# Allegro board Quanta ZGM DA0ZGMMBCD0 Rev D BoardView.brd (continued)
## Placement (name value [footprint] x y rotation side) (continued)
C515  100u/6.3V_12  [C1206]  23.57 55.15 0 top
C516  0.1u/6.3V_2  [C0201]  176.41 55.08 270 top
C517  *47u/6.3V_8  [C0805]  102.11 54.57 90 top
C518  *68p/25V_2  [C0201]  137.38 54.31 180 top
C519  *2.2u/10V_4  [C0402]  137.45 53.45 180 top
C520  470p/50V_4  [C0402]  20.23 53.25 270 top
C521  0.1u/6.3V_2  [C0201]  21.27 53.15 90 top
C522  *6.8p/50V_2  [C0201]  137.59 52.57 180 top
C523  *220p/25V_2  [C0201]  208.79 50.51 270 top
C524  *0.1u/6.3V_2  [C0201]  256.59 50.41 180 top
C525  0.1u/6.3V_2  [C0201]  21.41 48.59 0 top
C526  *0.1u/6.3V_2  [C0201]  212.2 47.79 180 top
C527  *68p/25V_2  [C0201]  137.78 47.68 180 top
C528  0.1u/6.3V_2  [C0201]  281.18 47.21 90 top
C529  0.1u/6.3V_2  [C0201]  281.94 47.21 90 top
C530  10u/6.3V_4  [C0402]  282.83 46.83 270 top
C531  *10u/6.3V_4  [C0402]  283.85 46.83 270 top
C532  *47u/6.3V_8  [C0805]  285.37 46.06 90 top
C533  *47u/6.3V_8  [C0805]  287.4 46.06 90 top
C534  0.1u/6.3V_2  [C0201]  193.55 45.56 270 top
C535  *6.8p/50V_2  [C0201]  271.06 45.42 90 top
C536  *68p/25V_2  [C0201]  271.77 45.41 90 top
C537  *2.2u/10V_4  [C0402]  225.4 45.26 90 top
C538  *220p/25V_2  [C0201]  207.78 45.25 90 top
C539  *68p/25V_2  [C0201]  224.53 45.22 90 top
C540  *68p/25V_2  [C0201]  226.28 45.18 90 top
C541  *1000p/25V_2  [C0201]  219.21 45.05 90 top
C542  0.1u/6.3V_2  [C0201]  183.01 44.92 0 top
C543  0.1u/6.3V_2  [C0201]  184.03 44.92 180 top
C544  0.1u/6.3V_2  [C0201]  17.02 42.7 0 top
C545  *1000p/25V_2  [C0201]  187.2 42.51 0 top
C546  220p/25V_2  [C0201]  13.74 41.85 90 top
C547  0.1u/6.3V_2  [C0201]  219.84 41.49 180 top
C548  0.1u/6.3V_2  [C0201]  217.55 41.2 180 top
C549  *6.8p/50V_2  [C0201]  285.64 40.09 270 top
C550  *6.8p/50V_2  [C0201]  286.36 40.07 270 top
C551  *1000p/25V_2  [C0201]  203.91 39.38 180 top
C552  0.1u/6.3V_2  [C0201]  206.17 39.08 180 top
C553  *220p/25V_2  [C0201]  13.97 38.7 90 top
C554  0.1u/6.3V_2  [C0201]  23.91 24.37 270 top
C555  0.1u/6.3V_2  [C0201]  24.15 21.97 180 top
C556  0.1u/6.3V_2  [C0201]  24.15 21.26 180 top
C557  10u/6.3V_4  [C0402]  16.87 21.17 270 top
C558  0.1u/6.3V_2  [C0201]  15.91 20.8 90 top
C559  220p/25V_2  [C0201]  19.49 10.39 270 top
C560  0.1u/6.3V_2  [C0201]  18.57 6.86 180 top
C561  0.1u/6.3V_2  [C0201]  19.56 6.86 0 top
C562  0.01u/50V_4  [C0402]  16.7 3.06 0 top
C563  0.01u/50V_4  [C0402]  19.87 3.06 180 top
C564  0.1u/6.3V_2  [C0201]  262.54 217.49 0 bottom
C565  0.1u/6.3V_2  [C0201]  277.71 216.02 270 bottom
C566  0.1u/6.3V_2  [C0201]  278.43 216.02 270 bottom
C567  0.1u/6.3V_2  [C0201]  274.85 216.02 270 bottom
C568  0.1u/6.3V_2  [C0201]  275.56 216.02 270 bottom
C569  0.1u/6.3V_2  [C0201]  276.28 216.02 270 bottom
C570  0.1u/6.3V_2  [C0201]  276.99 216.02 270 bottom
C571  0.1u/6.3V_2  [C0201]  271.99 215.95 270 bottom
C572  0.1u/6.3V_2  [C0201]  272.7 215.95 270 bottom
C573  0.1u/6.3V_2  [C0201]  270.24 215.57 270 bottom
C574  0.1u/6.3V_2  [C0201]  270.95 215.57 270 bottom
C575  0.1u/6.3V_2  [C0201]  142.75 214.34 270 bottom
C576  10u/6.3V_4  [C0402]  143.89 214.34 90 bottom
C577  0.1u/6.3V_2  [C0201]  269.85 213.58 0 bottom
C578  2200p/25V_2  [C0201]  259.82 213.15 0 bottom
C579  0.1u/6.3V_2  [C0201]  269.85 212.81 0 bottom
C580  0.1u/6.3V_2  [C0201]  269.85 212.1 0 bottom
C581  0.1u/6.3V_2  [C0201]  269.85 211.33 0 bottom
C582  0.1u/6.3V_2  [C0201]  272.67 209.12 270 bottom
C583  0.1u/6.3V_2  [C0201]  273.43 209.12 270 bottom
C584  0.1u/6.3V_2  [C0201]  271.19 209.12 270 bottom
C585  0.1u/6.3V_2  [C0201]  271.96 209.12 270 bottom
C586  0.1u/6.3V_2  [C0201]  275.35 209.09 270 bottom
C587  0.1u/6.3V_2  [C0201]  276.11 209.09 270 bottom
C588  0.1u/6.3V_2  [C0201]  276.82 209.09 270 bottom
C589  0.1u/6.3V_2  [C0201]  277.59 209.09 270 bottom
C590  0.1u/6.3V_2  [C0201]  278.31 209.09 90 bottom
C591  0.1u/6.3V_2  [C0201]  279.07 209.09 90 bottom
C592  10u/6.3V_4  [C0402]  145.91 208.04 90 bottom
C593  0.1u/6.3V_2  [C0201]  144.76 208.03 270 bottom
C594  0.1u/6.3V_2  [C0201]  266.36 207.74 270 bottom
C595  0.1u/6.3V_2  [C0201]  267.12 207.74 90 bottom
C596  *2.2u/10V_4  [C0402]  278.07 204.64 270 bottom
C597  1u/10V_2  [C0201]  286.51 202.24 270 bottom
C598  0.1u/6.3V_2  [C0201]  280.74 201.42 180 bottom
C599  0.1u/6.3V_2  [C0201]  268.13 200.65 90 bottom
C600  10u/6.3V_4  [C0402]  280.78 200.43 0 bottom
C601  0.1u/6.3V_2  [C0201]  268.13 198.87 270 bottom
C602  180p/25V_2  [C0201]  270.01 196.69 270 bottom
C603  *2.2u/25V_4  [C0402]  193.7 194.51 270 bottom
C604  *3.3p/25V_2  [C0201]  193.04 193.28 0 bottom
C605  *68p/25V_2  [C0201]  193.04 192.51 0 bottom
C606  0.1u/6.3V_2  [C0201]  269.08 185.98 270 bottom
C607  10u/25V_8  [C0805]  275.47 184.11 180 bottom
C608  *6.8p/50V_2  [C0201]  270.03 185.48 270 bottom
C609  1000p/25V_2  [C0201]  267.68 185.36 90 bottom
C610  *6.8p/50V_2  [C0201]  270.84 184.67 90 bottom
C611  22u/6.3V_6  [C0603]  202.87 183.91 0 bottom
C612  0.1u/6.3V_2  [C0201]  200.79 183.73 0 bottom
C613  0.1u/25V_2  [C0201]  270.01 183.6 90 bottom
C614  100p/50V_2  [C0201]  270.89 183.22 270 bottom
C615  10u/25V_8  [C0805]  273.38 181.37 0 bottom
C616  *10u/6.3V_4  [C0402]  198.55 182.46 0 bottom
C617  22u/6.3V_6  [C0603]  210.7 182.21 180 bottom
C618  0.047u/6.3V_2  [C0201]  200.88 181.97 90 bottom
C619  *1000p/25V_2  [C0201]  200.76 181.05 180 bottom
C620  0.1u/6.3V_2  [C0201]  206.57 175.48 270 bottom
C621  *10u/6.3V_4  [C0402]  205.51 175.38 90 bottom
C622  *68p/25V_2  [C0201]  111.27 175.3 270 bottom
C623  *68p/25V_2  [C0201]  112.04 175.29 270 bottom
C624  *2.2u/10V_4  [C0402]  110.34 175.27 270 bottom
C625  *6.8p/50V_2  [C0201]  206.98 173.41 90 bottom
C626  *6.8p/50V_2  [C0201]  206.01 173.39 90 bottom
C627  *6.8p/50V_2  [C0201]  262.67 172.08 0 bottom
C628  *6.8p/50V_2  [C0201]  262.68 171.32 0 bottom
C629  *2.2u/10V_4  [C0402]  149.49 168.23 0 bottom
C630  *6.8p/50V_2  [C0201]  149.46 167.36 0 bottom
C631  *6.8p/50V_2  [C0201]  149.47 166.55 0 bottom
C632  2200p/25V_2  [C0201]  189.49 166.3 90 bottom
C633  47u/6.3V_6  [C0603]  132.84 163.11 180 bottom
C634  0.1u/6.3V_2  [C0201]  150.16 162.11 90 bottom
C635  0.1u/6.3V_2  [C0201]  151.31 162.11 90 bottom
C636  0.1u/6.3V_2  [C0201]  152.63 161.82 90 bottom
C637  0.1u/6.3V_2  [C0201]  153.39 161.82 90 bottom
C638  0.1u/6.3V_2  [C0201]  155.72 161.67 90 bottom
C639  0.1u/6.3V_2  [C0201]  156.49 161.67 90 bottom
C640  0.1u/6.3V_2  [C0201]  159.03 161.67 90 bottom
C641  0.1u/6.3V_2  [C0201]  159.79 161.67 90 bottom
C642  0.1u/6.3V_2  [C0201]  161.62 161.63 90 bottom
C643  0.1u/6.3V_2  [C0201]  162.39 161.63 90 bottom
C644  47u/6.3V_6  [C0603]  127.18 161.51 180 bottom
C645  47u/6.3V_6  [C0603]  138.9 161.27 180 bottom
C646  0.1u/6.3V_2  [C0201]  157.36 160.83 90 bottom
C647  0.1u/6.3V_2  [C0201]  158.12 160.83 90 bottom
C648  47u/6.3V_6  [C0603]  132.76 160.81 180 bottom
C649  0.1u/6.3V_2  [C0201]  160.4 160.31 90 bottom
C650  0.1u/6.3V_2  [C0201]  161.16 160.31 90 bottom
C651  0.1u/6.3V_2  [C0201]  162.69 160.24 90 bottom
C652  0.1u/6.3V_2  [C0201]  163.45 160.24 90 bottom
C653  47u/6.3V_6  [C0603]  127.18 159.99 180 bottom
C654  47u/6.3V_6  [C0603]  139 159.16 180 bottom
C655  10p/25V_2  [C0201]  166.34 158.75 0 bottom
C656  10p/25V_2  [C0201]  166.34 157.86 0 bottom
C657  8.2p/50V_2  [C0201]  166.34 156.97 0 bottom
C658  10p/25V_2  [C0201]  123.59 155.57 270 bottom
C659  10p/25V_2  [C0201]  124.36 155.57 270 bottom
C660  47u/6.3V_6  [C0603]  122.36 151.68 270 bottom
C661  47u/6.3V_6  [C0603]  123.91 151.65 270 bottom
C662  47u/6.3V_6  [C0603]  120.5 147.44 270 bottom
C663  47u/6.3V_6  [C0603]  121.93 147.07 270 bottom
C664  0.1u/6.3V_2  [C0201]  114.4 144.32 90 bottom
C665  0.22u/6.3V_2  [C0201]  182.01 141.78 0 bottom
C666  0.22u/6.3V_2  [C0201]  182.01 141.02 0 bottom
C667  0.22u/6.3V_2  [C0201]  183.41 140.61 0 bottom
C668  0.22u/6.3V_2  [C0201]  183.41 139.85 0 bottom
C669  0.22u/6.3V_2  [C0201]  182.01 139.44 0 bottom
C670  0.22u/6.3V_2  [C0201]  182.01 138.68 0 bottom
C671  *6.8p/50V_2  [C0201]  276.14 138.55 270 bottom
C672  *6.8p/50V_2  [C0201]  275.33 138.54 270 bottom
C673  0.22u/6.3V_2  [C0201]  183.41 138.28 0 bottom
C674  0.22u/6.3V_2  [C0201]  183.41 137.51 0 bottom
C675  0.22u/6.3V_2  [C0201]  182.01 137.11 0 bottom
C676  0.22u/6.3V_2  [C0201]  182.01 136.35 0 bottom
C677  0.22u/6.3V_2  [C0201]  183.41 135.94 0 bottom
C678  0.22u/6.3V_2  [C0201]  183.41 135.18 0 bottom
C679  0.22u/6.3V_2  [C0201]  182.01 134.77 0 bottom
C680  0.22u/6.3V_2  [C0201]  182.01 134.01 0 bottom
C681  0.22u/6.3V_2  [C0201]  181.65 132.4 270 bottom
C682  0.22u/6.3V_2  [C0201]  182.41 132.4 270 bottom
C683  *6.8p/50V_2  [C0201]  197.26 128.35 180 bottom
C684  *6.8p/50V_2  [C0201]  197.25 127.54 180 bottom
C685  6.8p/50V_2  [C0201]  237.24 121.37 180 bottom
C686  *2.2u/10V_4  [C0402]  289.57 111.25 90 bottom
C687  *6.8p/50V_2  [C0201]  288.51 111.07 90 bottom
C688  *68p/25V_2  [C0201]  287.77 111.06 90 bottom
C689  2200p/25V_2  [C0201]  212.6 107.03 0 bottom
C690  220p/25V_2  [C0201]  106.77 104.88 90 bottom
C691  220p/25V_2  [C0201]  108.04 104.88 90 bottom
C692  0.1u/25V_2  [C0201]  109.31 104.88 270 bottom
C693  0.1u/6.3V_2  [C0201]  210.41 102.94 270 bottom
C694  0.1u/6.3V_2  [C0201]  309.41 99.29 270 bottom
C695  10u/6.3V_4  [C0402]  310.28 99.14 90 bottom
C696  0.1u/6.3V_2  [C0201]  311.12 98.53 90 bottom
C697  10u/6.3V_4  [C0402]  311.95 98.54 270 bottom
C698  0.1u/6.3V_2  [C0201]  309.32 96.47 270 bottom
C699  10u/6.3V_4  [C0402]  310.39 96.47 90 bottom
C700  10u/6.3V_4  [C0402]  36.11 95.76 180 bottom
C701  10u/6.3V_4  [C0402]  39.63 95.31 0 bottom
C702  2.2u/10V_4  [C0402]  36.11 94.79 180 bottom
C703  *3.3p/25V_2  [C0201]  95.25 94.38 180 bottom
C704  2.2u/10V_4  [C0402]  39.63 94.32 0 bottom
C705  *6.8p/50V_2  [C0201]  78.11 93.97 0 bottom
C706  18p/25V_2  [C0201]  36.41 93.96 0 bottom
C707  *68p/25V_2  [C0201]  95.25 93.61 180 bottom
C708  2.2u/10V_4  [C0402]  41.43 92.79 90 bottom
C709  *2.2u/10V_4  [C0402]  95.19 92.74 180 bottom
C710  47u/6.3V_6  [C0603]  36.44 92.28 270 bottom
C711  *68p/25V_2  [C0201]  49.22 91.79 180 bottom
C712  2.2u/10V_4  [C0402]  41.57 91.07 270 bottom
C713  *2.2u/10V_4  [C0402]  49.24 90.92 180 bottom
C714  10u/6.3V_4  [C0402]  312.35 89.92 0 bottom
C715  2.2u/10V_4  [C0402]  38.87 90.4 270 bottom
C716  5G@1u/10V_2  [C0201]  299.05 90.39 180 bottom
C717  2.2u/10V_4  [C0402]  36.44 90.11 90 bottom
C718  2.2u/10V_4  [C0402]  40.22 90.05 180 bottom
C719  *3.3p/25V_2  [C0201]  49.22 90.04 180 bottom
C720  0.1u/6.3V_2  [C0201]  313.67 89.83 270 bottom
C721  5G@0.22u/6.3V_2  [C0201]  310.65 89.42 0 bottom
C722  2.2u/10V_4  [C0402]  41.57 89.33 270 bottom
C723  5G@0.22u/6.3V_2  [C0201]  310.65 88.66 0 bottom
C724  2.2u/10V_4  [C0402]  36.44 88.38 270 bottom
C725  0.22u/6.3V_2  [C0201]  113.03 88.23 0 bottom
C726  0.22u/6.3V_2  [C0201]  113.03 87.47 0 bottom
C727  0.22u/6.3V_2  [C0201]  113.03 85.18 0 bottom
C728  *22p/25V_2  [C0201]  216.94 84.81 0 bottom
C729  *47p/25V_2  [C0201]  215.12 84.75 90 bottom
C730  0.22u/6.3V_2  [C0201]  113.03 84.42 0 bottom
C731  *0.1u/6.3V_2  [C0201]  214.02 83.99 180 bottom
C732  0.22u/6.3V_2  [C0201]  113.03 82.13 0 bottom
C733  0.22u/6.3V_2  [C0201]  113.03 81.37 0 bottom
C734  *2.2u/10V_4  [C0402]  100.16 80.94 90 bottom
C735  *68p/25V_2  [C0201]  99.3 80.56 90 bottom
C736  *6.8p/50V_2  [C0201]  98.58 80.56 90 bottom
C737  4.7u/6.3V_4  [C0402]  227.85 80.19 180 bottom
C738  0.22u/6.3V_2  [C0201]  113.03 79.08 0 bottom
C739  2.2u/10V_4  [C0402]  227.84 78.83 180 bottom
C740  0.22u/6.3V_2  [C0201]  113.03 78.32 0 bottom
C741  10u/6.3V_4  [C0402]  31.5 78.07 180 bottom
C742  2.2u/10V_4  [C0402]  35.06 78.04 0 bottom
C743  2.2u/10V_4  [C0402]  31.5 77.06 180 bottom
C744  10u/6.3V_4  [C0402]  35.06 77.05 0 bottom
C745  18p/25V_2  [C0201]  31.85 76.21 0 bottom
C746  2.2u/10V_4  [C0402]  36.86 75.52 90 bottom
C747  47u/6.3V_6  [C0603]  31.87 74.54 270 bottom
C748  *SUB@1000p/25V_2  [C0201]  290.15 74.39 270 bottom
C749  10u/6.3V_4  [C0402]  314.45 73.93 90 bottom
C750  2.2u/10V_4  [C0402]  36.86 73.72 270 bottom
C751  2.2u/10V_4  [C0402]  34.16 73.12 270 bottom
C752  2.2u/10V_4  [C0402]  35.51 72.78 180 bottom
C753  2.2u/10V_4  [C0402]  32.07 72.74 180 bottom
C754  2.2u/10V_4  [C0402]  36.86 71.99 270 bottom
C755  10u/6.3V_4  [C0402]  314.35 71.88 90 bottom
C756  2.2u/10V_4  [C0402]  31.97 71.09 270 bottom
C757  *SUB@1000p/25V_2  [C0201]  286.9 71.59 0 bottom
C758  *3.3p/25V_2  [C0201]  48.5 70.15 90 bottom
C759  *2.2u/10V_4  [C0402]  49.4 70.12 90 bottom
C760  *68p/25V_2  [C0201]  50.28 70.1 90 bottom
C761  *2.2u/10V_4  [C0402]  70.48 70 90 bottom
C762  0.1u/6.3V_2  [C0201]  314.34 69.94 180 bottom
C763  *3.3p/25V_2  [C0201]  71.39 69.93 90 bottom
C764  *68p/25V_2  [C0201]  69.59 69.9 90 bottom
C765  0.1u/6.3V_2  [C0201]  284.31 67.74 270 bottom
C766  0.1u/6.3V_2  [C0201]  285.07 67.74 270 bottom
C767  1u/10V_2  [C0201]  19.46 66.33 270 bottom
C768  1u/10V_2  [C0201]  21.11 66.33 270 bottom
C769  *68p/25V_2  [C0201]  96.5 66.26 270 bottom
C770  *6.8p/50V_2  [C0201]  97.26 66.26 270 bottom
C771  *2.2u/10V_4  [C0402]  98.12 66.23 270 bottom
C772  *0.1u/6.3V_2  [C0201]  314.76 65.62 180 bottom
C773  *10u/6.3V_4  [C0402]  310.29 65.53 0 bottom
C774  SUB@0.1u/6.3V_2  [C0201]  298.05 63.95 0 bottom
C775  10u/6.3V_4  [C0402]  311.34 63.21 90 bottom
C776  0.1u/6.3V_2  [C0201]  312.3 63.16 270 bottom
C777  0.22u/6.3V_2  [C0201]  112.4 62.83 0 bottom
C778  10u/6.3V_4  [C0402]  314.51 62.55 180 bottom
C779  0.1u/6.3V_2  [C0201]  18.95 62.17 90 bottom
C780  0.01u/10V_2  [C0201]  19.71 62.17 90 bottom
C781  0.22u/6.3V_2  [C0201]  112.4 62.07 0 bottom
C782  *1000p/25V_2  [C0201]  307.93 60.11 90 bottom
C783  0.22u/6.3V_2  [C0201]  112.4 59.78 0 bottom
C784  0.1u/6.3V_2  [C0201]  38.81 59.68 270 bottom
C785  0.1u/6.3V_2  [C0201]  40.34 59.68 270 bottom
C786  0.1u/6.3V_2  [C0201]  41.73 59.68 270 bottom
C787  0.1u/6.3V_2  [C0201]  43.38 59.68 270 bottom
C788  0.1u/6.3V_2  [C0201]  44.58 59.65 270 bottom
C789  5G@0.1u/25V_2  [C0201]  235.33 59.3 270 bottom
C790  0.1u/6.3V_2  [C0201]  191.15 59.24 0 bottom
C791  0.22u/6.3V_2  [C0201]  112.4 59.02 0 bottom
C792  *10p/25V_2  [C0201]  227.84 58.76 180 bottom
C793  5G@1u/10V_2  [C0201]  236.07 59.3 270 bottom
C794  0.1u/6.3V_2  [C0201]  21.23 58.13 270 bottom
C795  22p/25V_2  [C0201]  245.18 57.21 90 bottom
C796  0.1u/6.3V_2  [C0201]  246.81 57.06 90 bottom
C797  0.1u/6.3V_2  [C0201]  40.34 56.89 90 bottom
C798  0.1u/6.3V_2  [C0201]  43.38 56.89 90 bottom
C799  0.1u/6.3V_2  [C0201]  38.36 56.86 90 bottom
C800  0.1u/6.3V_2  [C0201]  39.37 56.86 90 bottom
C801  0.1u/6.3V_2  [C0201]  41.66 56.86 90 bottom
C802  4.7u/6.3V_4  [C0402]  42.55 56.86 270 bottom
C803  0.1u/6.3V_2  [C0201]  44.45 56.86 90 bottom
C804  0.22u/6.3V_2  [C0201]  112.4 56.73 0 bottom
C805  5G_S@0.1u/25V_2  [C0201]  279.68 56.45 0 bottom
C806  0.22u/6.3V_2  [C0201]  112.4 55.97 0 bottom
C807  0.1u/6.3V_2  [C0201]  227.59 55.97 90 bottom
C808  1u/10V_2  [C0201]  228.48 55.97 90 bottom
C809  5G_S@0.1u/25V_2  [C0201]  286.29 55.74 0 bottom
C810  5G_S@0.1u/25V_2  [C0201]  279.68 55.69 0 bottom
C811  10u/6.3V_4  [C0402]  98.81 55.08 0 bottom
C812  *6.8p/50V_2  [C0201]  19.18 55 270 bottom
C813  5G_S@0.1u/25V_2  [C0201]  286.29 54.98 0 bottom
C814  0.1u/6.3V_2  [C0201]  228.65 54.56 90 bottom
C815  10u/6.3V_4  [C0402]  227.55 54.56 270 bottom
C816  0.1u/6.3V_2  [C0201]  98.81 53.94 0 bottom
C817  1u/10V_2  [C0201]  25.44 53.89 270 bottom
C818  0.22u/6.3V_2  [C0201]  112.4 53.68 0 bottom
C819  *3.3p/25V_2  [C0201]  77.67 53.34 180 bottom
C820  0.1u/6.3V_2  [C0201]  98.81 53.18 0 bottom
C821  0.22u/6.3V_2  [C0201]  112.4 52.92 0 bottom
C822  0.033u/6.3V_2  [C0201]  211.55 52.42 270 bottom
C823  *2.2u/10V_4  [C0402]  77.68 52.42 180 bottom
C824  1u/10V_2  [C0201]  228.83 52.19 0 bottom
C825  1u/10V_2  [C0201]  230.13 52.16 270 bottom
C826  *3.3p/25V_2  [C0201]  77.66 51.51 180 bottom
C827  0.1u/6.3V_2  [C0201]  98.81 51.27 0 bottom
C828  15p/25V_2  [C0201]  218.62 50.77 0 bottom
C829  15p/25V_2  [C0201]  219.61 50.77 180 bottom
C830  0.1u/6.3V_2  [C0201]  98.81 50.51 0 bottom
C831  0.1u/6.3V_2  [C0201]  273.18 50.13 90 bottom
C832  0.1u/6.3V_2  [C0201]  273.94 50.13 90 bottom
C833  0.1u/6.3V_2  [C0201]  268.87 50.09 180 bottom
C834  1u/10V_2  [C0201]  230.13 49.87 90 bottom
C835  0.1u/6.3V_2  [C0201]  268.87 49.33 180 bottom
C836  0.1u/6.3V_2  [C0201]  276.48 49.24 0 bottom
C837  1u/10V_2  [C0201]  233.56 49.11 180 bottom
C838  0.1u/6.3V_2  [C0201]  276.48 48.35 0 bottom
C839  0.1u/6.3V_2  [C0201]  276.48 47.46 180 bottom
C840  18p/25V_2  [C0201]  220.07 45.78 270 bottom
C841  *1000p/25V_2  [C0201]  260.1 45.3 0 bottom
C842  *1000p/25V_2  [C0201]  262.13 45.3 180 bottom
C843  *1000p/25V_2  [C0201]  263.66 45.3 0 bottom
C844  *1000p/25V_2  [C0201]  265.56 45.3 180 bottom
C845  10u/6.3V_4  [C0402]  268.99 44.92 0 bottom
C846  0.1u/6.3V_2  [C0201]  271.53 42.76 90 bottom
C847  0.1u/6.3V_2  [C0201]  272.42 42.76 90 bottom
C848  0.1u/6.3V_2  [C0201]  273.31 42.76 90 bottom
C849  0.1u/6.3V_2  [C0201]  274.2 42.76 90 bottom
C850  0.1u/6.3V_2  [C0201]  18.62 27.14 270 bottom
C851  0.1u/6.3V_2  [C0201]  19.38 27.14 270 bottom
C852  0.1u/6.3V_2  [C0201]  20.15 27.14 270 bottom
C853  0.1u/6.3V_2  [C0201]  20.91 27.14 270 bottom
C854  0.1u/6.3V_2  [C0201]  21.67 27.14 270 bottom
C855  0.1u/6.3V_2  [C0201]  22.43 27.14 270 bottom
C856  0.1u/6.3V_2  [C0201]  23.19 27.14 270 bottom
C857  0.1u/6.3V_2  [C0201]  23.96 27.14 270 bottom
C858  *1u/10V_2  [C0201]  16.45 24.33 90 bottom
C859  0.1u/6.3V_2  [C0201]  17.22 24.33 90 bottom
C860  10u/6.3V_4  [C0402]  16.47 21.28 0 bottom
C861  0.1u/6.3V_2  [C0201]  19.19 18.25 90 bottom
C862  0.1u/6.3V_2  [C0201]  18.48 18.25 90 bottom
C863  0.1u/6.3V_2  [C0201]  22.62 18.25 90 bottom
C864  0.1u/6.3V_2  [C0201]  23.38 18.25 90 bottom
C865  0.1u/6.3V_2  [C0201]  21.25 18.25 90 bottom
C866  0.1u/6.3V_2  [C0201]  24.68 18.25 90 bottom
C867  0.1u/6.3V_2  [C0201]  25.44 18.25 90 bottom
C868  0.1u/6.3V_2  [C0201]  20.53 18.24 90 bottom
C871  0.22u/25V_2  [C0201]  202.95 73.88 90 top
C872  0.22u/25V_2  [C0201]  198.56 74.21 90 top
C873  *6.8p/50V_2  [C0201]  99.75 116.86 180 bottom
C874  *4.7u/6.3V_4  [C0402]  191.04 40.58 270 top
C875  *4.7u/6.3V_4  [C0402]  214.66 39.87 180 top
CG1  22u/6.3V_6  [C0603]  219.65 184.59 180 top
CG2  22u/6.3V_6  [C0603]  234.12 184.56 180 top
CG3  22u/6.3V_6  [C0603]  242.57 184.55 0 top
CG4  22u/6.3V_6  [C0603]  256.96 184.52 0 top
CG5  22u/6.3V_6  [C0603]  248.26 184.49 180 top
CG6  1u/10V_2  [C0201]  221.59 184.28 180 top
CG7  1u/10V_2  [C0201]  254.28 184.27 0 top
CG8  1u/10V_2  [C0201]  250.62 184.25 180 top
CG9  1u/10V_2  [C0201]  237.26 183.7 90 top
CG10  1u/10V_2  [C0201]  229.39 183.28 270 top
CG11  1u/10V_2  [C0201]  238.83 183.24 270 top
CG12  1u/10V_2  [C0201]  246.51 183.17 0 top
CG13  1u/10V_2  [C0201]  244.62 183.06 270 top
CG14  1u/10V_2  [C0201]  251.72 182.54 270 top
CG15  22u/6.3V_6  [C0603]  252.82 182.53 90 top
CG16  1u/10V_2  [C0201]  224.13 182.36 270 top
CG17  10u/6.3V_4  [C0402]  223.04 182.15 90 top
CG18  1u/10V_2  [C0201]  250.81 182.03 270 top
CG19  10u/6.3V_4  [C0402]  217.23 181.98 270 top
CG20  1u/10V_2  [C0201]  244 181.74 90 top
CG21  1u/10V_2  [C0201]  246.54 181.69 270 top
CG22  1u/10V_2  [C0201]  240.15 181.5 180 top
CG23  22u/6.3V_6  [C0603]  258.94 181.38 90 top
CG24  1u/10V_2  [C0201]  221.28 181.35 180 top
CG25  1u/10V_2  [C0201]  254.79 181.33 0 top
CG26  1u/10V_2  [C0201]  235.65 181.32 270 top
CG27  1u/10V_2  [C0201]  229.53 181.09 270 top
CG28  1u/10V_2  [C0201]  240.1 180.58 180 top
CG29  1u/10V_2  [C0201]  243.92 180.24 90 top
CG30  22u/6.3V_6  [C0603]  231.67 180.21 90 top
CG31  1u/10V_2  [C0201]  246.4 180.17 270 top
CG32  1u/10V_2  [C0201]  217.46 180.1 90 top
CG33  1u/10V_2  [C0201]  253.09 179.96 90 top
CG34  1u/10V_2  [C0201]  237.44 179.92 90 top
CG35  1u/10V_2  [C0201]  258.59 179.58 270 top
CG36  1u/10V_2  [C0201]  229.47 179.56 270 top
CG37  1u/10V_2  [C0201]  243.21 179.27 0 top
CG38  1u/10V_2  [C0201]  255.07 179.24 0 top
CG39  1u/10V_2  [C0201]  226.21 179.07 0 top
CG40  1u/10V_2  [C0201]  217.41 178.7 90 top
CG41  1u/10V_2  [C0201]  246.48 178.6 90 top
CG42  1u/10V_2  [C0201]  229.56 178.24 90 top
CG43  1u/10V_2  [C0201]  257.01 178.14 180 top
CG44  1u/10V_2  [C0201]  231.99 177.93 90 top
CG45  22u/6.3V_6  [C0603]  258.91 177.76 90 top
CG46  1u/10V_2  [C0201]  248.77 177.57 0 top
CG47  1u/10V_2  [C0201]  247.77 177.57 0 top
CG48  1u/10V_2  [C0201]  241.38 177.5 180 top
CG49  1u/10V_2  [C0201]  219.31 177.39 0 top
CG50  1u/10V_2  [C0201]  242.16 176.1 180 top
CG51  1u/10V_2  [C0201]  218.63 176 0 top
CG52  1u/10V_2  [C0201]  237.97 175.99 90 top
CG53  1u/10V_2  [C0201]  233.17 175.98 270 top
CG54  22u/6.3V_6  [C0603]  259.14 175.09 90 top
CG55  1u/10V_2  [C0201]  232.02 175.08 270 top
CG56  1u/10V_2  [C0201]  228.12 175.06 90 top
CG57  1u/10V_2  [C0201]  226.31 174.59 90 top
CG58  10u/6.3V_4  [C0402]  252.93 173.75 270 top
CG59  1u/10V_2  [C0201]  217.49 173.64 90 top
CG60  1u/10V_2  [C0201]  232.02 173.58 90 top
CG61  22u/6.3V_6  [C0603]  244.48 173.41 270 top
CG62  22u/6.3V_6  [C0603]  246.2 173.41 270 top
CG63  1u/10V_2  [C0201]  215.38 173.26 90 top
CG64  1u/10V_2  [C0201]  235.81 173.26 0 top
CG65  1u/10V_2  [C0201]  250.26 173.23 180 top
CG66  1u/10V_2  [C0201]  221.5 173.17 0 top
CG67  1u/10V_2  [C0201]  254.68 173.1 0 top
CG68  1u/10V_2  [C0201]  229.64 172.75 270 top
CG69  1u/10V_2  [C0201]  258.49 172.73 270 top
CG70  1u/10V_2  [C0201]  217.41 172.59 90 top
CG71  1u/10V_2  [C0201]  235.81 172.52 0 top
CG72  1u/10V_2  [C0201]  252.13 172.46 180 top
CG73  1u/10V_2  [C0201]  250.4 172.42 0 top
CG74  1u/10V_2  [C0201]  196.81 168.05 270 top
CG75  1u/10V_2  [C0201]  197.76 167.28 180 top
CG76  1u/10V_2  [C0201]  199.46 166.06 270 top
CG77  1u/10V_2  [C0201]  275.05 165.77 270 top
CG78  1u/10V_2  [C0201]  197.65 165.72 180 top
CG79  1u/10V_2  [C0201]  275.17 164.72 270 top
CG80  1u/10V_2  [C0201]  198.14 164.5 270 top
CG81  1u/10V_2  [C0201]  202.73 163.6 270 top
CG82  1u/10V_2  [C0201]  199.74 163.25 90 top
CG83  1u/10V_2  [C0201]  272.35 162.83 90 top
CG84  1u/10V_2  [C0201]  274.51 161.52 0 top
CG85  1u/10V_2  [C0201]  198.33 161.45 270 top
CG86  1u/10V_2  [C0201]  200.3 161.42 180 top
CG87  1u/10V_2  [C0201]  273.43 161.34 180 top
CG88  1u/10V_2  [C0201]  270.76 161.3 0 top
CG89  1u/10V_2  [C0201]  201.71 160.79 0 top
CG90  1u/10V_2  [C0201]  198.34 159.68 270 top
CG91  1u/10V_2  [C0201]  199.8 159.58 270 top
CG92  1u/10V_2  [C0201]  247.23 159.17 270 top
CG93  1u/10V_2  [C0201]  231.89 159.03 0 top
CG94  1u/10V_2  [C0201]  273.68 159 0 top
CG95  1u/10V_2  [C0201]  275.18 158.75 270 top
CG96  1u/10V_2  [C0201]  234.67 158.53 0 top
CG97  1u/10V_2  [C0201]  239.91 158.51 90 top
CG98  1u/10V_2  [C0201]  246.5 158.48 90 top
CG99  1u/10V_2  [C0201]  198.38 158.37 270 top
CG100  1u/10V_2  [C0201]  225.65 158.36 0 top
CG101  1u/10V_2  [C0201]  271.47 158.34 270 top
CG102  10u/6.3V_4  [C0402]  236.79 158.13 180 top
CG103  1u/10V_2  [C0201]  240.81 158.07 180 top
CG104  1u/10V_2  [C0201]  238.6 157.88 180 top
CG105  22u/6.3V_6  [C0603]  244.58 157.81 180 top
CG106  1u/10V_2  [C0201]  232.31 157.77 270 top
CG107  1u/10V_2  [C0201]  231.56 157.77 90 top
CG108  1u/10V_2  [C0201]  233.08 157.73 90 top
CG109  10u/6.3V_4  [C0402]  242.45 157.72 90 top
CG110  1u/10V_2  [C0201]  199.71 157.68 90 top
CG111  1u/10V_2  [C0201]  229.56 157.67 0 top
CG112  1u/10V_2  [C0201]  227.44 157.66 180 top
CG113  1u/10V_2  [C0201]  247.48 157.66 0 top
CG114  1u/10V_2  [C0201]  234 157.64 180 top
CG115  1u/10V_2  [C0201]  246.48 157.63 180 top
CG116  1u/10V_2  [C0201]  265.51 157.59 270 top
CG117  1u/10V_2  [C0201]  240.31 157.18 180 top
CG118  1u/10V_2  [C0201]  224.34 157.17 90 top
CG119  1u/10V_2  [C0201]  249.51 157.03 270 top
CG120  1u/10V_2  [C0201]  195.42 156.84 180 top
CG121  10u/6.3V_4  [C0402]  248.63 156.64 90 top
CG122  1u/10V_2  [C0201]  232.59 156.58 180 top
CG123  1u/10V_2  [C0201]  226.89 156.55 0 top
CG124  1u/10V_2  [C0201]  225.43 156.48 90 top
CG125  1u/10V_2  [C0201]  238.19 156.41 0 top
CG126  1u/10V_2  [C0201]  244.51 156.2 180 top
CG127  1u/10V_2  [C0201]  197.53 156.18 270 top
CG128  1u/10V_2  [C0201]  195.42 156.11 180 top
CG129  22u/6.3V_6  [C0603]  200.6 156.08 180 top
CG130  1u/10V_2  [C0201]  193.82 156.01 90 top
CG131  1u/10V_2  [C0201]  192.99 155.97 90 top
CG132  1u/10V_2  [C0201]  236.84 155.86 0 top
CG133  1u/10V_2  [C0201]  234.01 155.82 0 top
CG134  1u/10V_2  [C0201]  240.98 155.81 0 top
CG135  1u/10V_2  [C0201]  235.4 155.69 0 top
CG136  1u/10V_2  [C0201]  268.47 155.68 0 top
CG137  1u/10V_2  [C0201]  191.25 155.68 90 top
CG138  1u/10V_2  [C0201]  231.2 155.67 0 top
CG139  1u/10V_2  [C0201]  192.08 155.65 90 top
CG140  1u/10V_2  [C0201]  239.6 155.64 90 top
CG141  1u/10V_2  [C0201]  203.83 155.61 180 top
CG142  1u/10V_2  [C0201]  232.59 155.59 0 top
CG143  1u/10V_2  [C0201]  205.45 155.59 180 top
CG144  1u/10V_2  [C0201]  209.05 155.49 0 top
CG145  1u/10V_2  [C0201]  227.71 155.17 0 top
CG146  1u/10V_2  [C0201]  197.53 155.15 270 top
CG147  1u/10V_2  [C0201]  234.01 155.1 0 top
CG148  1u/10V_2  [C0201]  237.54 154.97 90 top
CG149  1u/10V_2  [C0201]  235.41 154.96 0 top
CG150  1u/10V_2  [C0201]  229.84 154.93 90 top
CG151  1u/10V_2  [C0201]  232.59 154.87 0 top
CG152  1u/10V_2  [C0201]  225.45 154.8 270 top
CG153  1u/10V_2  [C0201]  271.17 154.68 0 top
CG154  1u/10V_2  [C0201]  264.74 154.56 0 top
CG155  1u/10V_2  [C0201]  272.69 154.56 0 top
CG156  1u/10V_2  [C0201]  274.22 154.56 180 top
CG157  10u/6.3V_4  [C0402]  248.73 154.47 0 top
CG158  1u/10V_2  [C0201]  269.14 154.38 0 top
CG159  1u/10V_2  [C0201]  197.52 154.1 270 top
CG160  1u/10V_2  [C0201]  228.38 153.86 270 top
CG161  22u/6.3V_6  [C0603]  209.38 153.5 180 top
CG162  22u/6.3V_6  [C0603]  201.02 153.48 180 top
CG163  1u/10V_2  [C0201]  264.59 153.4 90 top
CG164  10u/6.3V_4  [C0402]  204.08 153.39 180 top
CG165  3.3p/25V_2  [C0201]  224.75 153.28 270 top
CG166  47u/6.3V_8  [C0805]  230.54 153.17 0 top
CG167  1u/10V_2  [C0201]  197.51 153.08 270 top
CG168  47u/6.3V_8  [C0805]  245.83 153.04 0 top
CG169  10u/6.3V_4  [C0402]  248.74 152.96 0 top
CG170  330U_2.5V_3528H2.1_max  [C3528]  241.59 152.57 0 top
CG171  330U_2.5V_3528H2.1_max  [C3528]  236 152.48 180 top
CG172  1u/10V_2  [C0201]  269.9 152.07 0 top
CG173  1u/10V_2  [C0201]  271.09 152.03 0 top
CG174  1u/10V_2  [C0201]  264.74 152.02 0 top
CG175  1u/10V_2  [C0201]  272.69 152.02 0 top
CG176  1u/10V_2  [C0201]  228.34 152.01 270 top
CG177  1u/10V_2  [C0201]  199.65 151.95 270 top
CG178  1u/10V_2  [C0201]  274.26 151.52 180 top
CG179  10u/6.3V_4  [C0402]  248.42 151.27 0 top
CG180  47u/6.3V_8  [C0805]  230.81 151.1 0 top
CG181  47u/6.3V_8  [C0805]  245.81 151.03 0 top
CG182  1u/10V_2  [C0201]  266.92 150.97 270 top
CG183  1u/10V_2  [C0201]  228.35 150.93 270 top
CG184  1u/10V_2  [C0201]  226.46 150.36 270 top
CG185  1u/10V_2  [C0201]  268.34 150.24 270 top
CG186  1u/10V_2  [C0201]  247.96 150.07 270 top
CG187  1u/10V_2  [C0201]  248.74 150.06 90 top
CG188  1u/10V_2  [C0201]  228.39 149.98 180 top
CG189  22u/6.3V_6  [C0603]  197.68 149.85 0 top
CG190  1u/10V_2  [C0201]  202.76 149.77 90 top
CG191  1u/10V_2  [C0201]  225.83 149.39 180 top
CG192  1u/10V_2  [C0201]  208.74 149.18 90 top
CG193  47u/6.3V_8  [C0805]  245.57 149.04 180 top
CG194  1u/10V_2  [C0201]  265.29 149.02 90 top
CG195  47u/6.3V_8  [C0805]  230.56 148.99 0 top
CG196  1u/10V_2  [C0201]  203.97 148.76 180 top
CG197  1u/10V_2  [C0201]  249.48 148.72 270 top
CG198  1u/10V_2  [C0201]  248.76 148.71 270 top
CG199  1u/10V_2  [C0201]  224.19 148.65 90 top
CG200  1u/10V_2  [C0201]  228.44 148.62 180 top
CG201  *330U_2.5V_3528H2.1_max  [C3528]  240.91 148.36 0 top
CG202  330U_2.5V_3528H2.1_max  [C3528]  234.78 148.26 180 top
CG203  1u/10V_2  [C0201]  272.22 148.01 180 top
CG204  1u/10V_2  [C0201]  275.18 148 90 top
CG205  1u/10V_2  [C0201]  226.94 147.89 180 top
CG206  22u/6.3V_6  [C0603]  197.62 147.87 0 top
CG207  1u/10V_2  [C0201]  201.82 147.68 0 top
CG208  1u/10V_2  [C0201]  200.78 147.67 180 top
CG209  10u/6.3V_4  [C0402]  247.95 147.23 0 top
CG210  10u/6.3V_4  [C0402]  245.24 147.19 180 top
CG211  47u/6.3V_8  [C0805]  230.45 146.97 0 top
CG212  1u/10V_2  [C0201]  226.24 146.95 180 top
CG213  1u/10V_2  [C0201]  273.33 146.91 180 top
CG214  10u/6.3V_4  [C0402]  201.8 146.5 180 top
CG215  10u/6.3V_4  [C0402]  197.62 146.42 0 top
CG216  1u/10V_2  [C0201]  226.02 145.96 180 top
CG217  1u/10V_2  [C0201]  227.07 145.9 90 top
CG218  1u/10V_2  [C0201]  246.6 145.7 180 top
CG219  1u/10V_2  [C0201]  268.59 145.54 180 top
CG220  1u/10V_2  [C0201]  270.61 145.46 0 top
CG221  1u/10V_2  [C0201]  273.2 145.42 180 top
CG222  1u/10V_2  [C0201]  247.97 145.33 0 top
CG223  10u/6.3V_4  [C0402]  236.09 145.25 0 top
CG224  1u/10V_2  [C0201]  199.71 145.18 270 top
CG225  10u/6.3V_4  [C0402]  233.32 145.13 0 top
CG226  10u/6.3V_4  [C0402]  244.55 145.13 0 top
CG227  10u/6.3V_4  [C0402]  241.7 145.13 0 top
CG228  10u/6.3V_4  [C0402]  238.92 145.12 180 top
CG229  10u/6.3V_4  [C0402]  230.49 145.09 0 top
CG230  10u/6.3V_4  [C0402]  197.52 145 0 top
CG231  1u/10V_2  [C0201]  228.34 144.85 90 top
CG232  1u/10V_2  [C0201]  248.56 144.58 0 top
CG233  1u/10V_2  [C0201]  275.13 144.33 270 top
CG234  1u/10V_2  [C0201]  271.62 144.1 270 top
CG235  1u/10V_2  [C0201]  225.5 144.1 270 top
CG236  1u/10V_2  [C0201]  264.9 143.86 90 top
CG237  1u/10V_2  [C0201]  246.59 143.77 90 top
CG238  10u/6.3V_4  [C0402]  236.1 143.72 0 top
CG239  10u/6.3V_4  [C0402]  241.69 143.71 0 top
CG240  4.7u/6.3V_4  [C0402]  233.32 143.71 0 top
CG241  10u/6.3V_4  [C0402]  238.92 143.71 0 top
CG242  10u/6.3V_4  [C0402]  244.54 143.67 0 top
CG243  10u/6.3V_4  [C0402]  230.53 143.66 0 top
CG244  22u/6.3V_6  [C0603]  197.5 143.47 0 top
CG245  1u/10V_2  [C0201]  226.43 143.4 90 top
CG246  1u/10V_2  [C0201]  228.36 143.37 90 top
CG247  1u/10V_2  [C0201]  206.65 143.32 90 top
CG248  1u/10V_2  [C0201]  248.57 143.29 0 top
CG249  1u/10V_2  [C0201]  199.81 142.97 90 top
CG250  1u/10V_2  [C0201]  208 142.94 0 top
CG251  1u/10V_2  [C0201]  226.37 142.3 270 top
CG252  10u/6.3V_4  [C0402]  236.12 142.22 0 top
CG253  1u/10V_2  [C0201]  267.58 142.08 90 top
CG254  1u/10V_2  [C0201]  246.63 141.91 90 top
CG255  10u/6.3V_4  [C0402]  233.3 141.69 0 top
CG256  10u/6.3V_4  [C0402]  230.5 141.68 0 top
CG257  10u/6.3V_4  [C0402]  241.7 141.68 180 top
CG258  10u/6.3V_4  [C0402]  244.51 141.64 180 top
CG259  10u/6.3V_4  [C0402]  238.88 141.62 180 top
CG260  1u/10V_2  [C0201]  228.43 141.58 90 top
CG261  22u/6.3V_6  [C0603]  199.69 141.45 180 top
CG262  1u/10V_2  [C0201]  202.21 141.1 180 top
CG263  1u/10V_2  [C0201]  203.86 141.1 180 top
CG264  1u/10V_2  [C0201]  205.13 141.1 180 top
CG265  1u/10V_2  [C0201]  248.68 140.83 0 top
CG266  1u/10V_2  [C0201]  264.68 140.8 90 top
CG267  1u/10V_2  [C0201]  228.44 140.56 90 top
CG268  1u/10V_2  [C0201]  246.52 140.35 90 top
CG269  10u/6.3V_4  [C0402]  230.5 140.25 0 top
CG270  10u/6.3V_4  [C0402]  244.5 140.22 180 top
CG271  4.7u/6.3V_4  [C0402]  233.32 140.21 180 top
CG272  10u/6.3V_4  [C0402]  236.06 140.21 0 top
CG273  10u/6.3V_4  [C0402]  241.7 140.21 180 top
CG274  10u/6.3V_4  [C0402]  238.9 140.19 0 top
CG275  1u/10V_2  [C0201]  271.87 140.18 180 top
CG276  1u/10V_2  [C0201]  225.9 140.11 0 top
CG277  1u/10V_2  [C0201]  270.44 140.11 180 top
CG278  1u/10V_2  [C0201]  265.72 140.03 180 top
CG279  22u/6.3V_6  [C0603]  274.3 139.89 0 top
CG280  1u/10V_2  [C0201]  264.66 139.76 90 top
CG281  1u/10V_2  [C0201]  248.63 139.64 0 top
CG282  1u/10V_2  [C0201]  227.11 139.55 90 top
CG283  1u/10V_2  [C0201]  246.5 139.36 90 top
CG284  1u/10V_2  [C0201]  240.96 139 90 top
CG285  1u/10V_2  [C0201]  242.35 139 90 top
CG286  1u/10V_2  [C0201]  239.61 139 90 top
CG287  1u/10V_2  [C0201]  229.83 138.99 90 top
CG288  1u/10V_2  [C0201]  245.16 138.98 90 top
CG289  1u/10V_2  [C0201]  243.71 138.93 90 top
CG290  22u/6.3V_6  [C0603]  204.29 138.92 180 top
CG291  22u/6.3V_6  [C0603]  201.63 138.92 0 top
CG292  *220p/25V_2  [C0201]  286.36 138.91 0 top
CG293  1u/10V_2  [C0201]  249.86 138.85 180 top
CG294  1u/10V_2  [C0201]  226.2 138.76 0 top
CG295  1u/10V_2  [C0201]  228.51 138.53 270 top
CG296  1u/10V_2  [C0201]  236.87 138.53 270 top
CG297  1u/10V_2  [C0201]  232.5 138.5 270 top
CG298  1u/10V_2  [C0201]  235.55 138.49 270 top
CG299  4.7u/6.3V_4  [C0402]  252.73 137.92 270 top
CG300  1u/10V_2  [C0201]  243.7 137.89 90 top
CG301  1u/10V_2  [C0201]  239.48 137.87 90 top
CG302  1u/10V_2  [C0201]  245.18 137.83 90 top
CG303  22u/6.3V_6  [C0603]  199.47 137.82 90 top
CG304  1u/10V_2  [C0201]  246.5 137.82 90 top
CG305  1u/10V_2  [C0201]  226.98 137.55 0 top
CG306  22u/6.3V_6  [C0603]  251.48 137.36 270 top
CG307  1u/10V_2  [C0201]  232.56 137.12 270 top
CG308  1u/10V_2  [C0201]  205 137.12 270 top
CG309  1u/10V_2  [C0201]  231.09 137.08 270 top
CG310  1u/10V_2  [C0201]  233.88 137.07 270 top
CG311  1u/10V_2  [C0201]  236.85 137.04 270 top
CG312  1u/10V_2  [C0201]  245.18 136.83 270 top
CG313  1u/10V_2  [C0201]  239.5 136.83 90 top
CG314  1u/10V_2  [C0201]  228.34 136.77 270 top
CG315  1u/10V_2  [C0201]  249.58 136.52 180 top
CG316  1u/10V_2  [C0201]  235.48 136.43 90 top
CG317  1u/10V_2  [C0201]  240.33 135.99 90 top
CG318  1u/10V_2  [C0201]  249.58 135.76 180 top
CG319  1u/10V_2  [C0201]  242.52 135.56 180 top
CG320  1u/10V_2  [C0201]  246.48 135.51 90 top
CG321  1u/10V_2  [C0201]  243.71 135.41 90 top
CG322  4.7u/6.3V_4  [C0402]  233.28 135.39 0 top
CG323  1u/10V_2  [C0201]  227.36 135.42 270 top
CG324  1u/10V_2  [C0201]  241.14 135.38 90 top
CG325  1u/10V_2  [C0201]  247.93 135.38 90 top
CG326  1u/10V_2  [C0201]  248.71 135.35 90 top
CG327  1u/10V_2  [C0201]  228.17 135.42 90 top
CG328  4.7u/6.3V_4  [C0402]  229.42 135.35 270 top
CG329  4.7u/6.3V_4  [C0402]  228.48 132.07 270 top
CG330  1u/10V_2  [C0201]  239.54 135.01 180 top
CG331  1u/10V_2  [C0201]  249.58 135 180 top
CG332  1u/10V_2  [C0201]  236.15 134.94 90 top
CG333  *220p/25V_2  [C0201]  277.14 134.87 180 top
CG334  1u/10V_2  [C0201]  238.03 134.71 0 top
CG335  4.7u/6.3V_4  [C0402]  245.26 134.67 270 top
CG336  1u/10V_2  [C0201]  242.85 134.62 180 top
CG337  1u/10V_2  [C0201]  199.75 134.25 90 top
CG338  1u/10V_2  [C0201]  241.52 134.14 180 top
CG339  1u/10V_2  [C0201]  239.07 133.95 90 top
CG340  1u/10V_2  [C0201]  252.91 133.94 270 top
CG341  1u/10V_2  [C0201]  253.67 133.94 270 top
CG342  1u/10V_2  [C0201]  243.08 133.91 0 top
CG343  4.7u/6.3V_4  [C0402]  248.6 133.9 180 top
CG344  1u/10V_2  [C0201]  237.57 133.86 0 top
CG345  1u/10V_2  [C0201]  236 133.81 270 top
CG346  1u/10V_2  [C0201]  231.16 133.6 270 top
CG347  1u/10V_2  [C0201]  228.5 133.5 90 top
CG348  1u/10V_2  [C0201]  229.72 133.5 270 top
CG349  1u/10V_2  [C0201]  200.86 133.42 0 top
CG350  1u/10V_2  [C0201]  232.74 133.35 270 top
CG351  1u/10V_2  [C0201]  233.96 133.35 270 top
CG352  1u/10V_2  [C0201]  235.23 133.35 270 top
CG353  1u/10V_2  [C0201]  241.58 133.35 180 top
CG354  1u/10V_2  [C0201]  244.04 133.17 180 top
CG355  1u/10V_2  [C0201]  245.89 132.97 0 top
CG356  22u/6.3V_6  [C0603]  238.33 132.71 0 top
CG357  1u/10V_2  [C0201]  227.66 134 270 top
CG358  1u/10V_2  [C0201]  248.11 132.58 270 top
CG359  1u/10V_2  [C0201]  201.63 131.74 0 top
CG360  *220p/25V_2  [C0201]  277.12 131.2 180 top
CG361  10u/6.3V_4  [C0402]  238.35 131.06 180 top
CG362  1u/10V_2  [C0201]  199.73 130.53 270 top
CG363  1u/10V_2  [C0201]  202.75 130.15 0 top
CG364  1u/10V_2  [C0201]  199.68 128.99 90 top
CG365  *220p/25V_2  [C0201]  277.14 127.63 180 top
CG366  1u/10V_2  [C0201]  199.77 127.55 0 top
CG367  1u/10V_2  [C0201]  250.34 121.03 180 top
CG368  1u/10V_2  [C0201]  251.91 120.98 0 top
CG369  4.7u/6.3V_4  [C0402]  237.4 120.94 0 top
CG370  0.22u/6.3V_2  [C0201]  220.11 120.88 270 top
CG371  0.22u/6.3V_2  [C0201]  220.88 120.88 270 top
CG372  0.22u/6.3V_2  [C0201]  222.65 120.88 270 top
CG373  0.22u/6.3V_2  [C0201]  223.42 120.88 270 top
CG374  0.22u/6.3V_2  [C0201]  225.19 120.88 270 top
CG375  0.22u/6.3V_2  [C0201]  225.96 120.88 270 top
CG376  0.22u/6.3V_2  [C0201]  227.73 120.88 270 top
CG377  0.22u/6.3V_2  [C0201]  228.5 120.88 270 top
CG378  1u/10V_2  [C0201]  251.91 120.27 0 top
CG379  1u/10V_2  [C0201]  250.34 120.24 180 top
CG380  1u/10V_2  [C0201]  237.45 120.1 180 top
CG381  1u/10V_2  [C0201]  251.91 119.56 0 top
CG382  *220p/25V_2  [C0201]  292.21 119.54 0 top
CG383  0.22u/6.3V_2  [C0201]  221.38 119.51 270 top
CG384  0.22u/6.3V_2  [C0201]  222.15 119.51 270 top
CG385  0.22u/6.3V_2  [C0201]  223.92 119.51 270 top
CG386  0.22u/6.3V_2  [C0201]  224.69 119.51 270 top
CG387  0.22u/6.3V_2  [C0201]  226.46 119.51 270 top
CG388  0.22u/6.3V_2  [C0201]  227.23 119.51 270 top
CG389  0.22u/6.3V_2  [C0201]  229 119.51 270 top
CG390  0.22u/6.3V_2  [C0201]  229.77 119.51 270 top
CG391  1u/10V_2  [C0201]  250.34 119.51 180 top
CG392  2.2u/10V_4  [C0402]  240.51 119.38 0 top
CG393  1u/10V_2  [C0201]  237.45 119.36 180 top
CG394  10u/6.3V_4  [C0402]  253.95 118.83 180 top
CG395  22u/6.3V_6  [C0603]  250.47 118.42 180 top
CG396  0.1u/6.3V_2  [C0201]  241.98 118.39 270 top
CG397  4.7u/6.3V_4  [C0402]  253.48 117.35 0 top
CG398  22u/6.3V_6  [C0603]  250.85 116.75 180 top
CG399  4.7u/6.3V_4  [C0402]  253.48 115.89 0 top
CG400  820p/50V_4  [C0402]  249.41 114.68 90 top
CG401  0.01u/10V_2  [C0201]  248.56 114.3 90 top
CG402  10u/6.3V_4  [C0402]  253.39 114.29 180 top
CG403  0.1u/6.3V_2  [C0201]  235.08 113.37 270 top
CG404  10u/6.3V_4  [C0402]  253.39 112.87 180 top
CG405  *0.1u/6.3V_2  [C0201]  243.12 112.02 0 top
CG406  4.7u/6.3V_4  [C0402]  225.94 136.13 180 top
CG407  22u/6.3V_6  [C0603]  225.43 134.91 180 top
CG408  1u/10V_2  [C0201]  227.26 133.08 0 top
CG409  1u/10V_2  [C0201]  230.72 186.15 90 bottom
CG410  1u/10V_2  [C0201]  231.55 186.12 90 bottom
CG411  1u/10V_2  [C0201]  243.55 186.02 90 bottom
CG412  1u/10V_2  [C0201]  242.79 186.02 90 bottom
CG413  1u/10V_2  [C0201]  244.3 186.02 90 bottom
CG414  22u/6.3V_6  [C0603]  227.74 185.83 180 bottom
CG415  22u/6.3V_6  [C0603]  217.95 185.8 180 bottom
CG416  22u/6.3V_6  [C0603]  222.53 185.8 180 bottom
CG417  10u/6.3V_4  [C0402]  234.46 185.8 180 bottom
CG418  10u/6.3V_4  [C0402]  237.26 185.8 180 bottom
CG419  10u/6.3V_4  [C0402]  239.93 185.8 0 bottom
CG420  10u/6.3V_4  [C0402]  241.92 185.76 90 bottom
CG421  10u/6.3V_4  [C0402]  232.43 185.67 90 bottom
CG422  22u/6.3V_6  [C0603]  262.63 185.58 180 bottom
CG423  10u/6.3V_4  [C0402]  248.31 185.55 180 bottom
CG424  10u/6.3V_4  [C0402]  251.48 185.55 180 bottom
CG425  22u/6.3V_6  [C0603]  255.42 185.55 180 bottom
CG426  10u/6.3V_4  [C0402]  258.72 185.42 0 bottom
CG427  22u/6.3V_6  [C0603]  262.63 184.06 180 bottom
CG428  22u/6.3V_6  [C0603]  214.27 183.89 0 bottom
CG429  10u/6.3V_4  [C0402]  262.63 182.62 180 bottom
CG430  22u/6.3V_6  [C0603]  214.27 182.37 0 bottom
CG431  10u/6.3V_4  [C0402]  262.63 181.1 180 bottom
CG432  10u/6.3V_4  [C0402]  214.27 180.85 0 bottom
CG433  10u/6.3V_4  [C0402]  262.63 179.62 180 bottom
CG434  10u/6.3V_4  [C0402]  214.27 179.32 0 bottom
CG435  1u/10V_2  [C0201]  262.44 178.5 0 bottom
CG436  10u/6.3V_4  [C0402]  214.14 177.93 180 bottom
CG437  1u/10V_2  [C0201]  262.43 177.55 0 bottom
CG438  10u/6.3V_4  [C0402]  214.14 176.66 180 bottom
CG439  10u/6.3V_4  [C0402]  262.51 176.24 180 bottom
CG440  22u/6.3V_6  [C0603]  262.51 174.71 180 bottom
CG441  10u/6.3V_4  [C0402]  211.46 174.59 270 bottom
CG442  10u/6.3V_4  [C0402]  213.11 174.59 270 bottom
CG443  22u/6.3V_6  [C0603]  262.51 173.19 180 bottom
CG444  1u/10V_2  [C0201]  197.51 170.69 180 bottom
CG445  1u/10V_2  [C0201]  197.51 169.92 180 bottom
CG446  22u/6.3V_6  [C0603]  263.66 169.63 180 bottom
CG447  10u/6.3V_4  [C0402]  204.92 169.52 90 bottom
CG448  1u/10V_2  [C0201]  276.14 169.29 90 bottom
CG449  1u/10V_2  [C0201]  276.87 169.28 90 bottom
CG450  1u/10V_2  [C0201]  277.59 169.16 90 bottom
CG451  1u/10V_2  [C0201]  197.51 169.16 180 bottom
CG452  22u/6.3V_6  [C0603]  268.74 169 270 bottom
CG453  22u/6.3V_6  [C0603]  270.26 169 270 bottom
CG454  22u/6.3V_6  [C0603]  273.27 168.99 270 bottom
CG455  22u/6.3V_6  [C0603]  274.72 168.99 270 bottom
CG456  22u/6.3V_6  [C0603]  271.82 168.98 270 bottom
CG457  10u/6.3V_4  [C0402]  200.9 169.07 270 bottom
CG458  10u/6.3V_4  [C0402]  202.35 169.07 270 bottom
CG459  10u/6.3V_4  [C0402]  203.62 169.07 270 bottom
CG460  22u/6.3V_6  [C0603]  197.51 168.02 0 bottom
CG461  10u/6.3V_4  [C0402]  277.14 167.89 180 bottom
CG462  10u/6.3V_4  [C0402]  197.63 166.62 180 bottom
CG463  10u/6.3V_4  [C0402]  277.14 166.37 180 bottom
CG464  10u/6.3V_4  [C0402]  197.63 165.35 180 bottom
CG465  22u/6.3V_6  [C0603]  277.14 164.84 180 bottom
CG466  22u/6.3V_6  [C0603]  197.63 163.83 0 bottom
CG467  22u/6.3V_6  [C0603]  277.14 163.32 180 bottom
CG468  22u/6.3V_6  [C0603]  197.63 162.18 0 bottom
CG469  10u/6.3V_4  [C0402]  277.2 162.04 180 bottom
CG470  22u/6.3V_6  [C0603]  197.63 160.53 0 bottom
CG471  10u/6.3V_4  [C0402]  277.25 160 180 bottom
CG472  22u/6.3V_6  [C0603]  197.63 158.88 0 bottom
CG473  10u/6.3V_4  [C0402]  277.24 157.35 180 bottom
CG474  22u/6.3V_6  [C0603]  197.63 157.22 0 bottom
CG475  1u/10V_2  [C0201]  197.51 156.08 180 bottom
CG476  1u/10V_2  [C0201]  197.51 155.32 180 bottom
CG477  10u/6.3V_4  [C0402]  277.26 155.28 180 bottom
CG478  1u/10V_2  [C0201]  277.19 154.44 0 bottom
CG479  1u/10V_2  [C0201]  197.51 154.43 180 bottom
CG480  1u/10V_2  [C0201]  197.51 153.54 180 bottom
CG481  22u/6.3V_6  [C0603]  277.14 153.29 180 bottom
CG482  22u/6.3V_6  [C0603]  197.51 152.4 0 bottom
CG483  22u/6.3V_6  [C0603]  277.14 151.64 180 bottom
CG484  10u/6.3V_4  [C0402]  197.67 150.8 0 bottom
CG485  10u/6.3V_4  [C0402]  277.17 149.93 180 bottom
CG486  22u/6.3V_6  [C0603]  197.51 149.1 0 bottom
CG487  22u/6.3V_6  [C0603]  277.14 148.46 180 bottom
CG488  10u/6.3V_4  [C0402]  197.51 147.45 0 bottom
CG489  22u/6.3V_6  [C0603]  277.13 146.98 180 bottom
CG490  10u/6.3V_4  [C0402]  197.51 145.79 0 bottom
CG491  22u/6.3V_6  [C0603]  277.14 145.23 180 bottom
CG492  10u/6.3V_4  [C0402]  197.51 144.14 0 bottom
CG493  10u/6.3V_4  [C0402]  277.17 143.72 180 bottom
CG494  10u/6.3V_4  [C0402]  197.51 142.49 0 bottom
CG495  10u/6.3V_4  [C0402]  277.16 141.72 180 bottom
CG496  1u/10V_2  [C0201]  197.51 141.35 180 bottom
CG497  1u/10V_2  [C0201]  197.51 140.59 180 bottom
CG498  10u/6.3V_4  [C0402]  277.17 139.68 180 bottom
CG499  22u/6.3V_6  [C0603]  197.41 139.5 0 bottom
CG500  22u/6.3V_6  [C0603]  269.05 138.14 90 bottom
CG501  10u/6.3V_4  [C0402]  270.91 138.59 90 bottom
CG502  10u/6.3V_4  [C0402]  272.38 138.58 90 bottom
CG503  10u/6.3V_4  [C0402]  197.36 137.39 0 bottom
CG504  *220p/25V_2  [C0201]  263.53 136.49 270 bottom
CG505  10u/6.3V_4  [C0402]  197.4 135.82 0 bottom
CG506  10u/6.3V_4  [C0402]  197.41 134.24 0 bottom
CG507  10u/6.3V_4  [C0402]  197.33 132.64 0 bottom
CG508  10u/6.3V_4  [C0402]  197.26 131.04 0 bottom
CG509  10u/6.3V_4  [C0402]  197.21 129.41 0 bottom
CG510  1u/10V_2  [C0201]  201.06 125.09 0 bottom
CG511  1u/10V_2  [C0201]  202.59 125.09 180 bottom
CG512  1u/10V_2  [C0201]  203.98 125.09 180 bottom
CG513  1u/10V_2  [C0201]  205.25 125.09 180 bottom
CG514  1u/10V_2  [C0201]  209.32 125.09 0 bottom
CG515  1u/10V_2  [C0201]  211.1 125.09 0 bottom
CG516  1u/10V_2  [C0201]  212.75 125.09 0 bottom
CG517  1u/10V_2  [C0201]  214.14 125.09 180 bottom
CG518  0.1u/6.3V_2  [C0201]  269.84 125.08 270 bottom
CG519  10p/25V_2  [C0201]  255.9 122.34 180 bottom
CG520  10p/25V_2  [C0201]  257.94 122.33 0 bottom
CG521  *47p/25V_2  [C0201]  252.37 121.04 90 bottom
CG522  *47p/25V_2  [C0201]  253.08 121.04 90 bottom
CG523  4.7u/6.3V_4  [C0402]  237.23 120.52 0 bottom
CG524  10u/6.3V_4  [C0402]  237.23 119.53 0 bottom
CG525  0.1u/6.3V_2  [C0201]  253.62 118.48 0 bottom
CG526  22u/6.3V_6  [C0603]  237.26 118.31 180 bottom
CG527  10u/6.3V_4  [C0402]  237.27 117.12 0 bottom
CG528  0.01u/50V_4  [C0402]  247.04 115.67 90 bottom
CN1  51619-0260N-001  [51619-0260N-001-26P-L]  263.55 195.3 270 top
CN2  GS12401-1011P-7H  [GS12401-1011-9H-40P-R]  272.1 193.6 90 top
CN3  50273-0040N-V10  [WTB-50273-0040N-V10-4P-L]  107.88 99.6 180 bottom
CN4  50224-01001-001  [50224-01001-001-10P-L]  317.7 95.91 270 bottom
CN5  UCF3M-51N30-0P10  [UB31-UCF3M-51N30-0P10-24P-SMT]  8.78 92.97 90 bottom
CN6  NASM0-S6701-TS40  [NGFF-NASM0-S6701-TS40-75P-KM]  104.33 84.48 90 bottom
CN7  5G@NASB0-S6701-TS58  [NGFF-NASB0-S6701-TS58-75P-KB]  306.2 84 270 bottom
CN8  50273-0040N-V10  [WTB-50273-0040N-V10-4P-L]  293.48 82.62 330 bottom
CN9  UCF3M-51N30-0P10  [UB31-UCF3M-51N30-0P10-24P-SMT]  8.78 78.97 90 bottom
CN10  51695-0450M-V01  [FPC-51695-0450M-V01-45P-L]  319.3 75.41 270 bottom
CN11  SUB@50273-0020N-V09  [50273-0020N-V09-2P-L]  295.2 73 270 bottom
CN12  NASE0-S6701-TSH4  [NGFF-NASE0-S6701-TSH4-KE-SMT]  277.76 70.24 90 bottom
CN13  NASM0-S6701-TS40  [NGFF-NASM0-S6701-TS40-75P-KM]  104.33 59.43 90 bottom
CN14  50273-00604-V09  [50273-00604-V09-6P-L]  261.53 54.1 0 bottom
CN15  31105-00902-V01  [UB31-31105-00902-V01-9P]  5.87 52.55 90 bottom
CN16  50273-0020N-V09  [50273-0020N-V09-2P-L]  225.03 48.34 0 bottom
CN17  51653-0100N-V01  [51653-0100N-V01-10P-L]  200.75 43.2 180 bottom
CN18  GS12201-1011-7H  [WTB-GS12201-1011-7H-20P-L-SMT]  282.8 43.2 270 bottom
CN19  51625-01201-001  [51625-01201-001-12P-L]  184.9 41.86 180 bottom
CN20  50271-0040N-V01  [50271-0040N-V01-4P-L]  265.28 40.1 180 bottom
CN21  50224-00801-001  [50224-00801-001-8P-L]  215.4 39.7 180 bottom
CN22  50273-00604-V09  [50273-00604-V09-6P-L]  41.12 34.1 180 bottom
CN23  HERA7-AK120D  [HDMI-HERA7-AK120D-19P]  3.99 33 90 bottom
CN24  C17732-12029-L  [DP-C17732-12023-L-20P-SMT]  13.45 15.16 90 bottom
D1  *AZ5725-01F.R7G  [ESD-1X0_6-2P]  268.39 196.38 270 top
D2  *AZ5725-01F.R7G  [ESD-1X0_6-2P]  277.5 193.41 90 top
D3  *AZ5725-01F.R7G  [ESD-1X0_6-2P]  268.2 192.93 90 top
D4  *AZ5725-01F.R7G  [ESD-1X0_6-2P]  277.37 191.4 270 top
D5  *AZ5725-01F.R7G  [ESD-1X0_6-2P]  268.18 190.87 270 top
D6  MESD05N92ULA  [DFN1006-3-1X0_6-0_55H-3P-SMT]  277.96 189.74 180 top
D7  *AZ5725-01F.R7G  [ESD-1X0_6-2P]  268.13 189.06 270 top
D8  *AZ5725-01F.R7G  [ESD-1X0_6-2P]  268.13 187.24 270 top
D9  ESD5311Z-2/TR  [D-0_6X0_3-0_34H]  31.75 93.63 90 top
D10  MESD05N92ULA  [DFN1006-3-1X0_6-0_55H-3P-SMT]  11.28 93.47 180 top
D11  ESD5311Z-2/TR  [D-0_6X0_3-0_34H]  31.75 92.65 270 top
D12  ESD5311Z-2/TR  [D-0_6X0_3-0_34H]  31.75 91.55 90 top
D13  ESD5311Z-2/TR  [D-0_6X0_3-0_34H]  31.75 90.57 270 top
D14  ESD5311Z-2/TR  [D-0_6X0_3-0_34H]  31.75 89.47 90 top
D15  5G@RB751S40  [D-1_2X0_8-0_65H]  311.29 89.37 180 top
D16  ESD5311Z-2/TR  [D-0_6X0_3-0_34H]  31.75 88.49 270 top
D17  ESD5311Z-2/TR  [D-0_6X0_3-0_34H]  31.75 87.38 90 top
D18  *5G@RB751S40  [D-1_2X0_8-0_65H]  309.93 86.95 0 top
D19  ESD5311Z-2/TR  [D-0_6X0_3-0_34H]  31.75 86.41 270 top
D20  RB500V-40  [D-SOD323-1_85X1_25-0_95H]  308.34 83.89 270 top
D21  RB500V-40  [D-SOD323-1_85X1_25-0_95H]  308.34 80.34 90 top
D22  MESD05N92ULA  [DFN1006-3-1X0_6-0_55H-3P-SMT]  12.97 79.52 0 top
D23  AZ5725-01F.R7G  [ESD-1X0_6-2P]  315.56 77.9 0 top
D24  AZ5725-01F.R7G  [ESD-1X0_6-2P]  173.05 77.72 90 top
D25  RB500V-40  [D-SOD323-1_85X1_25-0_95H]  318.58 76.91 90 top
D26  RB500V-40  [D-SOD323-1_85X1_25-0_95H]  320.44 76.91 90 top
D27  ESD5311Z-2/TR  [D-0_6X0_3-0_34H]  27.18 76.36 90 top
D28  ESD5311Z-2/TR  [D-0_6X0_3-0_34H]  27.18 75.38 270 top
D29  ESD5311Z-2/TR  [D-0_6X0_3-0_34H]  27.18 74.28 90 top
D30  ESD5311Z-2/TR  [D-0_6X0_3-0_34H]  27.18 73.3 270 top
D31  SUB@RB500V-40  [D-SOD323-1_85X1_25-0_95H]  291.71 73.11 180 top
D32  ESD5311Z-2/TR  [D-0_6X0_3-0_34H]  27.18 72.19 90 top
D33  ESD5311Z-2/TR  [D-0_6X0_3-0_34H]  27.18 71.22 270 top
D34  RB500V-40  [D-SOD323-1_85X1_25-0_95H]  160.79 71.21 270 top
D35  ESD5311Z-2/TR  [D-0_6X0_3-0_34H]  27.18 70.11 90 top
D36  *SDM20U30-7  [D-1_2X0_8-0_7H]  158.12 69.71 0 top
D37  SUB@RB500V-40  [D-SOD323-1_85X1_25-0_95H]  289.86 69.34 0 top
D38  ESD5311Z-2/TR  [D-0_6X0_3-0_34H]  27.18 69.13 270 top
D39  SDM20U30-7  [D-1_2X0_8-0_7H]  158.12 68.29 0 top
D40  SDM20U30-7  [D-1_2X0_8-0_7H]  158.12 66.87 0 top
D41  *SDM20U30-7  [D-1_2X0_8-0_7H]  159.52 65.12 0 top
D42  *SDM20U30-7  [D-1_2X0_8-0_7H]  159.52 63.71 0 top
D43  *SDM20U30-7  [D-1_2X0_8-0_7H]  159.52 62.19 0 top
D44  *SDM20U30-7  [D-1_2X0_8-0_7H]  159.52 60.67 0 top
D45  5G_S@RB500V-40  [D-SOD323-1_85X1_25-0_95H]  281.69 57.87 90 top
D46  ESD5311Z-2/TR  [D-0_6X0_3-0_34H]  19.61 55.08 0 top
D47  ESD5311Z-2/TR  [D-0_6X0_3-0_34H]  18.59 55.06 180 top
D48  ESD5311Z-2/TR  [D-0_6X0_3-0_34H]  18.65 49.92 180 top
D49  ESD5311Z-2/TR  [D-0_6X0_3-0_34H]  19.67 49.92 0 top
D50  *RB500V-40  [D-SOD323-1_85X1_25-0_95H]  263.84 215.83 90 bottom
D51  RB500V-40  [D-SOD323-1_85X1_25-0_95H]  139.89 214.25 180 bottom
D52  RB500V-40  [D-SOD323-1_85X1_25-0_95H]  142.9 206.1 270 bottom
D53  *AZ5725-01F.R7G  [ESD-1X0_6-2P]  266.2 198.59 180 bottom
D54  *AZ5725-01F.R7G  [ESD-1X0_6-2P]  268.99 196.56 270 bottom
D55  MESMAF20A  [D-3_8X2_5]  14.48 99.53 0 bottom
D56  *RB500V-40  [D-SOD323-1_85X1_25-0_95H]  215.24 99.07 270 bottom
D57  MESD05N92ULA  [DFN1006-3-1X0_6-0_55H-3P-SMT]  11.34 93.49 180 bottom
D58  MESD05N92ULA  [DFN1006-3-1X0_6-0_55H-3P-SMT]  11.85 91.65 0 bottom
D59  MESD05N92ULA  [DFN1006-3-1X0_6-0_55H-3P-SMT]  11.36 79.51 180 bottom
D60  MESD05N92ULA  [DFN1006-3-1X0_6-0_55H-3P-SMT]  11.72 77.68 0 bottom
D61  5G@AZ5725-01F.R7G  [ESD-1X0_6-2P]  311.12 76.53 0 bottom
D62  MESMAF20A  [D-3_8X2_5]  11.81 70.45 270 bottom
D63  5G@AZ5725-01F.R7G  [ESD-1X0_6-2P]  237.34 58.59 0 bottom
D64  5G@AZ5725-01F.R7G  [ESD-1X0_6-2P]  239.6 58.61 180 bottom
D65  5G@AZ5725-01F.R7G  [ESD-1X0_6-2P]  241.1 58.21 270 bottom
D66  AZ5725-01F.R7G  [ESD-1X0_6-2P]  20.23 58.12 90 bottom
D67  5G@AZ5725-01F.R7G  [ESD-1X0_6-2P]  312.84 87.07 0 bottom
D68  5G@AZ5725-01F.R7G  [ESD-1X0_6-2P]  312.83 85.64 0 bottom
D69  5G@AZ5725-01F.R7G  [ESD-1X0_6-2P]  311.46 84.06 270 bottom
D70  5G_S@RB500V-40  [D-SOD323-1_85X1_25-0_95H]  271.91 56.73 180 bottom
D71  BAT54CW  [SOT23-1_7-65-3P]  233.94 46.32 270 bottom
D72  MESD05N92ULA  [DFN1006-3-1X0_6-0_55H-3P-SMT]  20.78 46.3 270 bottom
